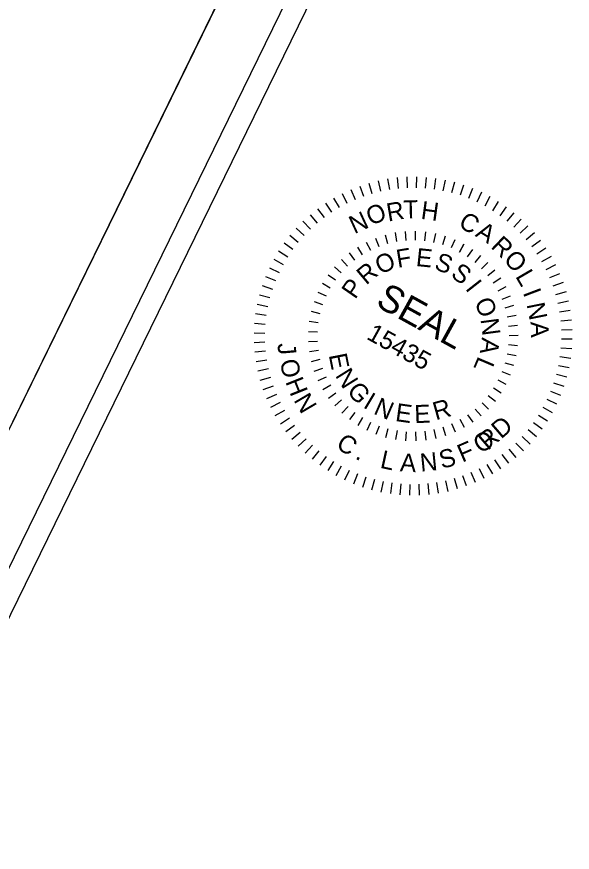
# Model space of a CAD drawing. Extents: x 1517888 to 1526099, y 633375 to 640181.
# Drawn here: x 1522953.6 to 1523182.2, y 634903.4 to 635247.1 of the extents above; entities that cross this region are included whole.
import ezdxf

# ---------------------------------------------------------------- set-up
doc = ezdxf.new("R2010")
doc.units = 0
for name, color, linetype in [('Old_Level_21', 7, 'Continuous'), ('Sheet Plan CELL', 7, 'Continuous'), ('Sheet Plot Border Inside CELL', 7, 'Continuous'), ('Sheet Plot Border Outside CELL', 7, 'Continuous')]:
    doc.layers.add(name, color=color, linetype=linetype)

msp = doc.modelspace()

# ---------------------------------------------------------------- linework, layer by layer
at = {"layer": 'Old_Level_21'}
for p, q in [((1523114.11, 635181.2), (1523114.29, 635176.73)), ((1523118.07, 635181.23), (1523117.97, 635176.77)), ((1523122.02, 635181.03), (1523121.65, 635176.58)), ((1523098.52, 635178.66), (1523099.76, 635174.38)), ((1523102.35, 635179.65), (1523103.33, 635175.3)), ((1523106.24, 635180.4), (1523106.95, 635176)), ((1523110.16, 635180.92), (1523110.61, 635176.48)), ((1523125.95, 635180.6), (1523125.32, 635176.17)), ((1523129.84, 635179.92), (1523128.95, 635175.54)), ((1523133.7, 635179.01), (1523132.54, 635174.7)), ((1523137.49, 635177.87), (1523136.07, 635173.64)), ((1523087.48, 635174.35), (1523089.47, 635170.36)), ((1523091.07, 635176.01), (1523092.82, 635171.91)), ((1523094.76, 635177.45), (1523096.26, 635173.25)), ((1523141.19, 635176.5), (1523139.53, 635172.37)), ((1523144.82, 635174.91), (1523142.9, 635170.88)), ((1523084, 635172.48), (1523086.22, 635168.61)), ((1523148.34, 635173.11), (1523146.19, 635169.2)), ((1523151.75, 635171.1), (1523149.36, 635167.32)), ((1523077.4, 635168.12), (1523080.08, 635164.55)), ((1523080.63, 635170.4), (1523083.09, 635166.68)), ((1523155.02, 635168.88), (1523152.42, 635165.26)), ((1523074.3, 635165.65), (1523077.2, 635162.25)), ((1523158.16, 635166.47), (1523155.34, 635163.02)), ((1523161.15, 635163.88), (1523158.12, 635160.6)), ((1523071.37, 635163.01), (1523074.47, 635159.78)), ((1523163.98, 635161.11), (1523160.75, 635158.01)), ((1523066.01, 635157.19), (1523069.46, 635154.37)), ((1523068.6, 635160.17), (1523071.88, 635157.15)), ((1523105.23, 635157.36), (1523106.22, 635153.77)), ((1523109.3, 635158.28), (1523109.94, 635154.61)), ((1523113.44, 635158.8), (1523113.72, 635155.08)), ((1523117.61, 635158.91), (1523117.53, 635155.19)), ((1523121.77, 635158.63), (1523121.33, 635154.93)), ((1523125.89, 635157.94), (1523125.09, 635154.3)), ((1523166.63, 635158.18), (1523163.22, 635155.28)), ((1523063.6, 635154.05), (1523067.22, 635151.44)), ((1523097.45, 635154.38), (1523099.11, 635151.04)), ((1523101.27, 635156.06), (1523102.6, 635152.58)), ((1523129.91, 635156.85), (1523128.77, 635153.31)), ((1523133.81, 635155.39), (1523132.34, 635151.98)), ((1523137.56, 635153.56), (1523135.77, 635150.3)), ((1523135.77, 635150.3), (1523137.56, 635153.56)), ((1523169.09, 635155.08), (1523165.53, 635152.4)), ((1523061.39, 635150.78), (1523065.16, 635148.39)), ((1523093.82, 635152.34), (1523095.79, 635149.18)), ((1523141.11, 635151.37), (1523139.01, 635148.3)), ((1523171.38, 635151.85), (1523167.65, 635149.39)), ((1523059.37, 635147.37), (1523063.28, 635145.21)), ((1523087.21, 635147.25), (1523089.76, 635144.54)), ((1523090.39, 635149.95), (1523092.66, 635147.01)), ((1523144.44, 635148.85), (1523142.05, 635145.99)), ((1523173.46, 635148.48), (1523169.59, 635146.26)), ((1523057.57, 635143.84), (1523061.6, 635141.93)), ((1523084.31, 635144.26), (1523087.11, 635141.8)), ((1523147.5, 635146.02), (1523144.85, 635143.41)), ((1523175.33, 635145), (1523171.33, 635143.01)), ((1523055.98, 635140.22), (1523060.11, 635138.55)), ((1523081.71, 635140.99), (1523084.73, 635138.83)), ((1523150.28, 635142.91), (1523147.39, 635140.57)), ((1523176.98, 635141.41), (1523172.88, 635139.66)), ((1523054.61, 635136.51), (1523058.84, 635135.1)), ((1523079.44, 635137.5), (1523082.65, 635135.62)), ((1523152.74, 635139.54), (1523149.64, 635137.49)), ((1523178.42, 635137.72), (1523174.22, 635136.22)), ((1523077.51, 635133.8), (1523080.89, 635132.24)), ((1523154.87, 635135.96), (1523151.58, 635134.21)), ((1523179.64, 635133.96), (1523175.35, 635132.72)), ((1523053.47, 635132.73), (1523057.78, 635131.56)), ((1523075.96, 635129.93), (1523079.47, 635128.71)), ((1523156.65, 635132.18), (1523153.2, 635130.76)), ((1523180.62, 635130.13), (1523176.27, 635129.15)), ((1523052.56, 635128.87), (1523056.94, 635127.97)), ((1523158.04, 635128.25), (1523154.48, 635127.17)), ((1523181.37, 635126.24), (1523176.97, 635125.53)), ((1523051.88, 635124.98), (1523056.31, 635124.35)), ((1523074.77, 635125.92), (1523078.39, 635125.05)), ((1523159.05, 635124.21), (1523155.41, 635123.48)), ((1523051.45, 635121.04), (1523055.9, 635120.68)), ((1523073.99, 635121.83), (1523077.67, 635121.3)), ((1523159.68, 635120.08), (1523155.97, 635119.7)), ((1523181.89, 635122.32), (1523177.45, 635121.87)), ((1523051.25, 635117.09), (1523055.71, 635117)), ((1523073.61, 635117.68), (1523077.32, 635117.52)), ((1523159.89, 635115.92), (1523156.17, 635115.9)), ((1523182.17, 635118.37), (1523177.71, 635118.19)), ((1523051.28, 635113.13), (1523055.75, 635113.32)), ((1523073.62, 635113.51), (1523077.33, 635113.7)), ((1523182.21, 635114.41), (1523177.74, 635114.51)), ((1523051.56, 635109.19), (1523056, 635109.64)), ((1523074.03, 635109.36), (1523077.72, 635109.91)), ((1523159.71, 635111.75), (1523156, 635112.09)), ((1523182, 635110.46), (1523177.56, 635110.83)), ((1523052.08, 635105.27), (1523056.48, 635105.98)), ((1523074.86, 635105.27), (1523078.46, 635106.17)), ((1523159.11, 635107.62), (1523155.46, 635108.33)), ((1523181.57, 635106.53), (1523177.14, 635107.16)), ((1523052.83, 635101.38), (1523057.19, 635102.36)), ((1523076.06, 635101.28), (1523079.57, 635102.53)), ((1523158.14, 635103.57), (1523154.57, 635104.62)), ((1523180.9, 635102.64), (1523176.52, 635103.53)), ((1523053.82, 635097.55), (1523058.1, 635098.79)), ((1523077.65, 635097.42), (1523081.02, 635099)), ((1523156.76, 635099.63), (1523153.32, 635101.02)), ((1523179.98, 635098.78), (1523175.67, 635099.94)), ((1523055.03, 635093.79), (1523059.23, 635095.28)), ((1523079.6, 635093.74), (1523082.8, 635095.63)), ((1523155.02, 635095.84), (1523151.72, 635097.55)), ((1523178.84, 635094.99), (1523174.61, 635096.41)), ((1523056.47, 635090.1), (1523060.57, 635091.85)), ((1523081.9, 635090.25), (1523084.91, 635092.45)), ((1523152.92, 635092.23), (1523149.8, 635094.26)), ((1523177.47, 635091.29), (1523173.34, 635092.95)), ((1523058.13, 635086.51), (1523062.12, 635088.5)), ((1523084.53, 635087.01), (1523087.31, 635089.49)), ((1523147.73, 635085.71), (1523145.06, 635088.3)), ((1523147.65, 635091.27), (1523150.57, 635088.96)), ((1523175.89, 635087.66), (1523171.86, 635089.58)), ((1523060, 635083.03), (1523063.87, 635085.25)), ((1523089.95, 635086.79), (1523087.43, 635084.05)), ((1523144.68, 635082.86), (1523142.27, 635085.7)), ((1523174.08, 635084.14), (1523170.17, 635086.29)), ((1523062.08, 635079.66), (1523065.8, 635082.12)), ((1523090.65, 635081.36), (1523092.89, 635084.32)), ((1523094.09, 635079), (1523096.03, 635082.17)), ((1523137.85, 635078.11), (1523136.02, 635081.35)), ((1523141.38, 635080.33), (1523139.26, 635083.38)), ((1523172.07, 635080.73), (1523168.3, 635083.12)), ((1523064.36, 635076.43), (1523067.93, 635079.11)), ((1523097.74, 635076.99), (1523099.38, 635080.33)), ((1523101.57, 635075.34), (1523102.88, 635078.82)), ((1523130.22, 635074.76), (1523129.06, 635078.28)), ((1523134.11, 635076.24), (1523132.61, 635079.65)), ((1523169.85, 635077.46), (1523166.23, 635080.06)), ((1523066.83, 635073.33), (1523070.23, 635076.23)), ((1523105.54, 635074.07), (1523106.5, 635077.66)), ((1523109.61, 635073.18), (1523110.23, 635076.85)), ((1523113.76, 635072.7), (1523114.02, 635076.41)), ((1523117.93, 635072.61), (1523117.83, 635076.33)), ((1523122.09, 635072.93), (1523121.63, 635076.61)), ((1523126.2, 635073.64), (1523125.38, 635077.27)), ((1523167.45, 635074.32), (1523163.99, 635077.14)), ((1523069.47, 635070.4), (1523072.7, 635073.5)), ((1523162.08, 635068.5), (1523158.98, 635071.73)), ((1523164.85, 635071.33), (1523161.57, 635074.36)), ((1523072.31, 635067.63), (1523075.33, 635070.91)), ((1523075.29, 635065.03), (1523078.11, 635068.49)), ((1523159.15, 635065.85), (1523156.26, 635069.26)), ((1523078.43, 635062.63), (1523081.04, 635066.25)), ((1523081.71, 635060.41), (1523084.09, 635064.19)), ((1523152.82, 635061.11), (1523150.36, 635064.83)), ((1523156.05, 635063.39), (1523153.37, 635066.95)), ((1523085.11, 635058.4), (1523087.27, 635062.31)), ((1523145.97, 635057.15), (1523143.98, 635061.15)), ((1523149.45, 635059.02), (1523147.23, 635062.89)), ((1523088.64, 635056.59), (1523090.55, 635060.62)), ((1523092.26, 635055.01), (1523093.93, 635059.14)), ((1523095.97, 635053.64), (1523097.38, 635057.87)), ((1523138.69, 635054.06), (1523137.2, 635058.26)), ((1523142.38, 635055.5), (1523140.63, 635059.6)), ((1523099.75, 635052.5), (1523100.92, 635056.81)), ((1523103.61, 635051.58), (1523104.51, 635055.96)), ((1523107.5, 635050.91), (1523108.13, 635055.34)), ((1523111.44, 635050.48), (1523111.8, 635054.92)), ((1523115.39, 635050.27), (1523115.48, 635054.74)), ((1523119.35, 635050.31), (1523119.16, 635054.77)), ((1523123.29, 635050.59), (1523122.84, 635055.03)), ((1523127.21, 635051.11), (1523126.5, 635055.51)), ((1523131.1, 635051.86), (1523130.12, 635056.21)), ((1523134.93, 635052.85), (1523133.69, 635057.13))]:
    msp.add_line(p, q, dxfattribs=at)
at = {"layer": 'Sheet Plan CELL'}
for points in [[(1523067.8, 635317.31), (1520372.85, 636635.35), (1519450.22, 634748.89), (1522145.17, 633430.84)], [(1522686.38, 635448.09), (1523045.79, 635272.3), (1522946.94, 635070.18), (1522587.52, 635245.97)], [(1522686.38, 635448.09), (1523045.79, 635272.3), (1522946.95, 635070.21), (1522587.53, 635245.99)]]:
    msp.add_lwpolyline(points, close=True, dxfattribs=at)
at = {"layer": 'Sheet Plot Border Inside CELL'}
msp.add_lwpolyline([(1519172.24, 634879.28), (1522165.43, 633415.37), (1523092.46, 635310.82), (1520099.27, 636774.73)], close=True, dxfattribs=at)
at = {"layer": 'Sheet Plot Border Outside CELL'}
msp.add_lwpolyline([(1519131.31, 634854.77), (1522155.94, 633375.48), (1523118.12, 635342.8), (1520093.48, 636822.08)], close=True, dxfattribs=at)

# ---------------------------------------------------------------- texts
at = {"layer": 'Old_Level_21'}
for s, height, rotation, p in [('R', 7.43, 9.7975, (1523106.45, 635162.84)), ('T', 7.43, 1.6366, (1523112.84, 635164.07)), ('H', 7.43, 352.2046, (1523119.64, 635164.01)), ('O', 7.43, 22.8543, (1523099.32, 635161.05)), ('N', 7.43, 24.8137, (1523092.54, 635157.61)), ('C', 7.43, 328.4939, (1523134.9, 635161.05)), ('A', 7.43, 328.4939, (1523141.95, 635157)), ('R', 7.43, 316.4846, (1523148.32, 635152.24)), ('F', 7.43, 9.3776, (1523110.41, 635143.79)), ('E', 7.43, 354.0813, (1523117.65, 635144.6)), ('O', 7.43, 313.4278, (1523153.59, 635146.89)), ('O', 7.43, 24.6738, (1523103.19, 635140.93)), ('S', 7.43, 338.7851, (1523125, 635143.47)), ('R', 7.43, 39.9701, (1523097.39, 635136.5)), ('S', 7.43, 323.4888, (1523131.8, 635140.43)), ('L', 7.43, 300.2915, (1523158.62, 635140.34)), ('P', 7.43, 55.2663, (1523092.85, 635130.59)), ('SEAL', 11.16, 331.137, (1523100.83, 635128.34)), ('I', 7.43, 308.1926, (1523137.95, 635135.21)), ('I', 7.43, 290.7161, (1523161.78, 635133.66)), ('O', 7.43, 292.8963, (1523141.8, 635129.78)), ('N', 7.43, 281.4216, (1523163.35, 635128.8)), ('N', 7.43, 277.6001, (1523144.41, 635122.65)), ('15435', 7.434, 331.137, (1523097.15, 635114.75)), ('A', 7.43, 271.6541, (1523165, 635121.62)), ('J', 7.43, 275.072, (1523060.9, 635112.63)), ('A', 7.43, 262.3039, (1523145.04, 635115.35)), ('O', 7.43, 283.1438, (1523061.76, 635105.39)), ('E', 7.43, 281.2071, (1523081.99, 635107.94)), ('L', 7.43, 247.0076, (1523143.6, 635107.74)), ('N', 7.43, 302.0621, (1523084.47, 635099.5)), ('H', 7.43, 291.7865, (1523064.05, 635096.98)), ('G', 7.43, 310.8284, (1523089.16, 635092.93)), ('N', 7.43, 300.4591, (1523067.4, 635089.4)), ('I', 7.43, 328.9232, (1523095.77, 635086.57)), ('N', 7.43, 336.5528, (1523100.06, 635083.92)), ('R', 7.43, 15.7019, (1523126.03, 635081.04)), ('E', 7.43, 351.9449, (1523109.11, 635080.83)), ('E', 7.43, 1.9308, (1523117.32, 635079.92)), (' RD', 7.434, 40.8094, (1523145.38, 635066.67)), ('C', 7.43, 327.2269, (1523084.56, 635070.01)), ('O ', 7.434, 32.1366, (1523144.42, 635067.17)), ('F', 7.43, 23.344, (1523136.93, 635063.62)), ('L', 7.43, 347.7536, (1523102.81, 635061.6)), ('N', 7.43, 5.5788, (1523119.89, 635059.92)), ('S', 7.43, 14.4614, (1523128.47, 635061.08)), ('.', 7.43, 334.9693, (1523092.55, 635065.38)), ('A', 7.43, 356.7561, (1523111.17, 635060.1))]:
    msp.add_text(s, height=height, rotation=rotation, dxfattribs=at).set_placement(p)

doc.saveas('drawing.dxf')
